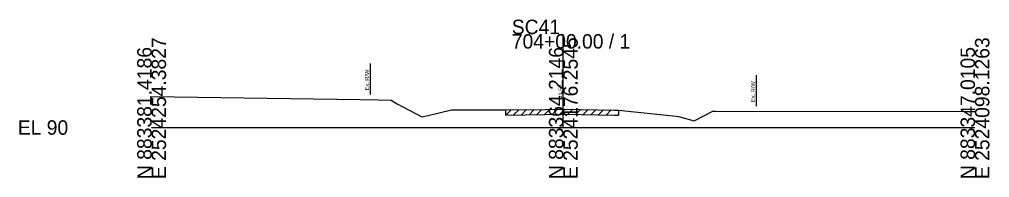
# Model space of a CAD drawing. Extents: x -26 to 183, y -10 to 24021.
# Drawn here: x -25.7 to 162.8, y 23990.3 to 24020.9 of the extents above; entities that cross this region are included whole.
import ezdxf

# ---------------------------------------------------------------- set-up
doc = ezdxf.new("R2010")
doc.units = 0
for name, color, linetype in [('RD_GPK_XS_Cell', 7, 'Continuous'), ('RD_XS_ExGround', 7, 'Continuous'), ('RD_XS_ExPaveRet', 7, 'Continuous'), ('RD_XS_ExRW', 7, 'Continuous'), ('RD_XS_TX_Elev_EX', 7, 'Continuous')]:
    doc.layers.add(name, color=color, linetype=linetype)

msp = doc.modelspace()

# ---------------------------------------------------------------- linework, layer by layer
at = {"layer": 'RD_GPK_XS_Cell'}
for p, q in [((80, 24000), (80, 24018.1)), ((0, 24000), (80, 24000)), ((80, 24000), (160, 24000))]:
    msp.add_line(p, q, dxfattribs=at)
at = {"layer": 'RD_XS_ExGround'}
for p, q in [((0, 24006.03), (40.47, 24005.42)), ((40.47, 24005.42), (44.12, 24005.37)), ((44.12, 24005.37), (46.55, 24005.31)), ((46.55, 24005.31), (47.73, 24004.62)), ((47.73, 24004.62), (52.51, 24002.06)), ((52.51, 24002.06), (53.71, 24002.34)), ((53.71, 24002.34), (58.29, 24003.42)), ((58.29, 24003.42), (63.34, 24003.45)), ((63.34, 24003.45), (68.85, 24003.42)), ((68.85, 24003.42), (76.47, 24003.52)), ((76.47, 24003.52), (80.25, 24003.58)), ((80.25, 24003.58), (89.96, 24003.39)), ((89.96, 24003.39), (90.74, 24003.37)), ((90.74, 24003.37), (101.95, 24002.18)), ((101.95, 24002.18), (102.37, 24002.14)), ((102.37, 24002.14), (105.41, 24001.27)), ((105.41, 24001.27), (109.08, 24003.15)), ((109.08, 24003.15), (109.64, 24003.15)), ((109.64, 24003.15), (157.89, 24003.12)), ((157.89, 24003.12), (160, 24003.11))]:
    msp.add_line(p, q, dxfattribs=at)
at = {"layer": 'RD_XS_ExPaveRet'}
for p, q in [((68.85, 24002.42), (69.86, 24003.43)), ((68.85, 24002.42), (68.85, 24003.42)), ((68.85, 24002.42), (76.47, 24002.52)), ((70.35, 24002.44), (71.36, 24003.45)), ((71.85, 24002.46), (72.86, 24003.47)), ((73.35, 24002.48), (74.36, 24003.5)), ((74.85, 24002.5), (75.86, 24003.52)), ((76.35, 24002.52), (77.36, 24003.54)), ((76.47, 24002.52), (80.25, 24002.58)), ((77.85, 24002.54), (78.86, 24003.56)), ((79.35, 24002.56), (80.36, 24003.57)), ((80.25, 24002.58), (89.96, 24002.39)), ((80.85, 24002.57), (81.83, 24003.55)), ((82.35, 24002.54), (83.33, 24003.52)), ((83.85, 24002.51), (84.83, 24003.49)), ((85.35, 24002.48), (86.33, 24003.46)), ((86.85, 24002.45), (87.83, 24003.43)), ((88.35, 24002.42), (89.33, 24003.4)), ((89.96, 24002.39), (90.74, 24002.37)), ((90.74, 24003.37), (90.74, 24002.37))]:
    msp.add_line(p, q, dxfattribs=at)
at = {"layer": 'RD_XS_ExRW'}
for p, q in [((42.5, 24012.39), (42.5, 24006.39)), ((117.5, 24010.14), (117.5, 24004.14))]:
    msp.add_line(p, q, dxfattribs=at)

# ---------------------------------------------------------------- texts
at = {"layer": 'RD_GPK_XS_Cell'}
for s, p in [('SC41', (70, 24018.1)), ('704+00.00 / 1', (70, 24015.3)), ('EL 90', (-26, 23998.6))]:
    msp.add_text(s, height=2.8, dxfattribs=at).set_placement(p)
for s, p in [('E 2524254.3827', (2.8, 23990)), ('E 2524176.2545', (82.8, 23990)), ('E 2524098.1263', (162.8, 23990)), ('N 883381.4186', (0, 23990)), ('N 883364.2146', (80, 23990)), ('N 883347.0105', (160, 23990))]:
    msp.add_text(s, height=2.8, rotation=90, dxfattribs=at).set_placement(p)
at = {"layer": 'RD_XS_ExRW'}
for p in [(42.25, 24007.18), (117.25, 24004.93)]:
    msp.add_text('Ex. R/W ', height=0.8, rotation=90, dxfattribs=at).set_placement(p)
at = {"layer": 'RD_XS_TX_Elev_EX'}
msp.add_text('93.57', height=0.8, rotation=90, dxfattribs=at).set_placement((79.9, 24005.57))

doc.saveas('drawing.dxf')
